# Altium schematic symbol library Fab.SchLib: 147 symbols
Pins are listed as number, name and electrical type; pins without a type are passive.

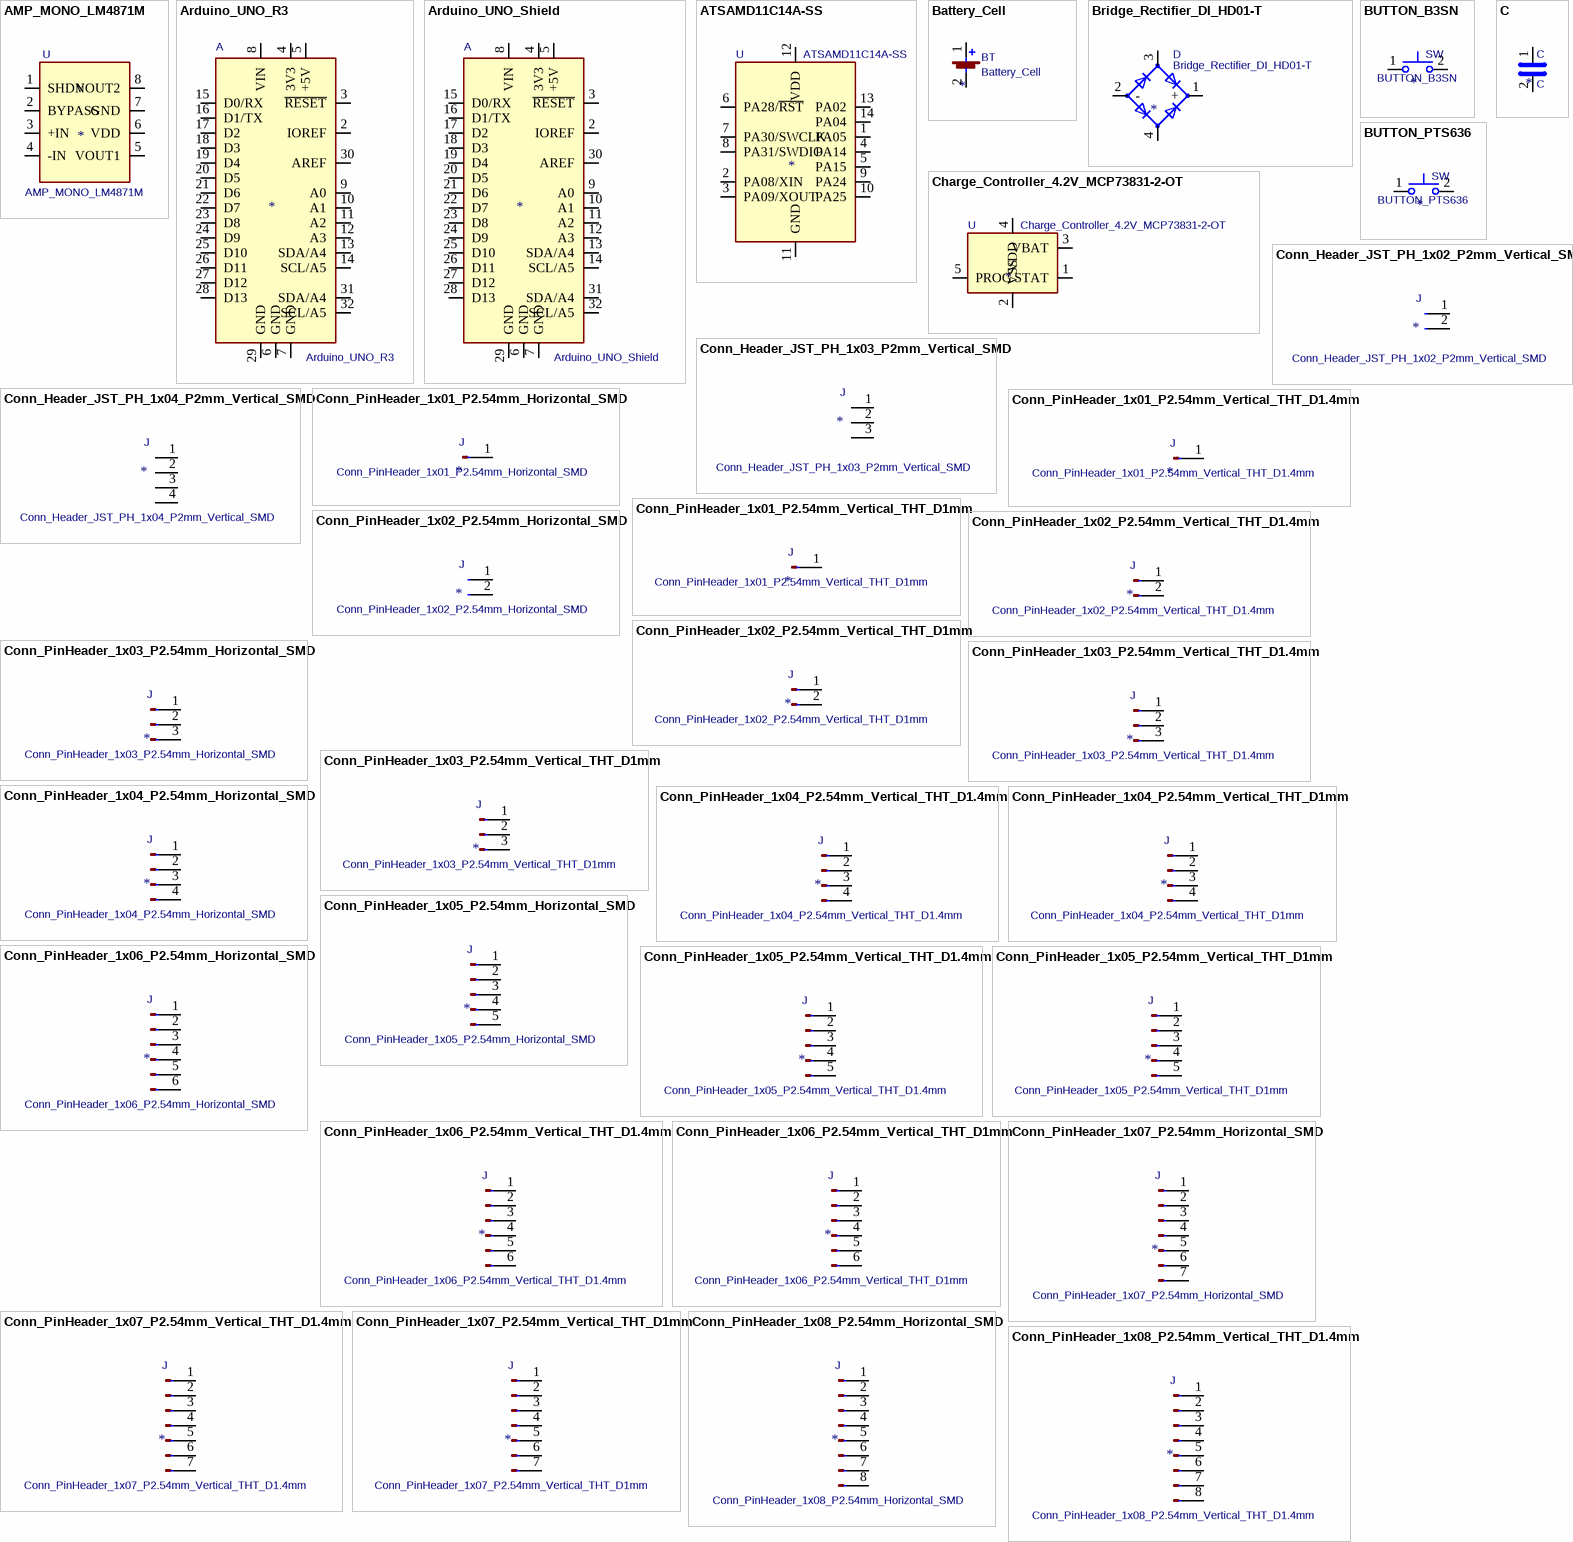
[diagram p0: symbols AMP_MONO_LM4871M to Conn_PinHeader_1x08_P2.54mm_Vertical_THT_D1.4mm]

## AMP_MONO_LM4871M
designator U  value AMP_MONO_LM4871M
footprint SOIC-8_3.9x4.9mm_P1.27mm
pins: 1 SHDN, 2 BYPASS, 3 +IN, 4 -IN, 5 VOUT1, 6 VDD, 7 GND, 8 VOUT2

## Arduino_UNO_R3
designator A  value Arduino_UNO_R3
footprint Arduino_UNO_R3_WithMountingHoles
pins: 1 NC hidden, 2 IOREF, 3 ~{RESET}, 4 3V3, 5 +5V, 6 GND, 7 GND, 8 VIN, 9 A0, 10 A1, 11 A2, 12 A3, 13 SDA/A4, 14 SCL/A5, 15 D0/RX, 16 D1/TX, 17 D2, 18 D3, 19 D4, 20 D5, 21 D6, 22 D7, 23 D8, 24 D9, 25 D10, 26 D11, 27 D12, 28 D13, 29 GND, 30 AREF, 31 SDA/A4, 32 SCL/A5

## Arduino_UNO_Shield
designator A  value Arduino_UNO_Shield
footprint Arduino_UNO_Shield
pins: 1 NC hidden, 2 IOREF, 3 ~{RESET}, 4 3V3, 5 +5V, 6 GND, 7 GND, 8 VIN, 9 A0, 10 A1, 11 A2, 12 A3, 13 SDA/A4, 14 SCL/A5, 15 D0/RX, 16 D1/TX, 17 D2, 18 D3, 19 D4, 20 D5, 21 D6, 22 D7, 23 D8, 24 D9, 25 D10, 26 D11, 27 D12, 28 D13, 29 GND, 30 AREF, 31 SDA/A4, 32 SCL/A5

## ATSAMD11C14A-SS
designator U  value ATSAMD11C14A-SS
footprint SOIC-14_3.9x8.7mm_P1.27mm
pins: 1 PA05, 2 PA08/XIN, 3 PA09/XOUT, 4 PA14, 5 PA15, 6 PA28/~{RST}, 7 PA30/SWCLK, 8 PA31/SWDIO, 9 PA24, 10 PA25, 11 GND, 12 VDD, 13 PA02, 14 PA04

## Battery_Cell
designator BT  value Battery_Cell
footprint Coin-Battery-Holder_Linx_BAT-HLD-001_D20mm
pins: 1 +, 2 -

## Bridge_Rectifier_DI_HD01-T
designator D  value Bridge_Rectifier_DI_HD01-T
footprint Bridge_Rectifier_DI_HD01-T
pins: 1 +, 2 -, 3, 4

## BUTTON_B3SN
designator SW  value BUTTON_B3SN
footprint Button_Omron_B3SN_6x6mm
pins: 1, 2

## BUTTON_PTS636
designator SW  value BUTTON_PTS636
footprint Button_C&K_PTS636_6x3.5mm
pins: 1, 2

## C
designator C  value C
footprint C_1206
pins: 1, 2

## Charge_Controller_4.2V_MCP73831-2-OT
designator U  value Charge_Controller_4.2V_MCP73831-2-OT
footprint SOT-23-5
pins: 1 STAT, 2 VSS, 3 VBAT, 4 VDD, 5 PROG

## Conn_Header_JST_PH_1x02_P2mm_Vertical_SMD
designator J  value Conn_Header_JST_PH_1x02_P2mm_Vertical_SMD
footprint Header_JST_PH_1x02_P2mm_Vertical_SMD
pins: 1, 2

## Conn_Header_JST_PH_1x03_P2mm_Vertical_SMD
designator J  value Conn_Header_JST_PH_1x03_P2mm_Vertical_SMD
footprint Header_JST_PH_1x03_P2mm_Vertical_SMD
pins: 1, 2, 3

## Conn_Header_JST_PH_1x04_P2mm_Vertical_SMD
designator J  value Conn_Header_JST_PH_1x04_P2mm_Vertical_SMD
footprint Header_JST_PH_1x04_P2mm_Vertical_SMD
pins: 1, 2, 3, 4

## Conn_PinHeader_1x01_P2.54mm_Horizontal_SMD
designator J  value Conn_PinHeader_1x01_P2.54mm_Horizontal_SMD
footprint PinHeader_1x01_P2.54mm_Horizontal_SMD
pins: 1 Pin_1

## Conn_PinHeader_1x01_P2.54mm_Vertical_THT_D1.4mm
designator J  value Conn_PinHeader_1x01_P2.54mm_Vertical_THT_D1.4mm
footprint PinHeader_1x01_P2.54mm_Vertical_THT_D1.4mm
pins: 1 Pin_1

## Conn_PinHeader_1x01_P2.54mm_Vertical_THT_D1mm
designator J  value Conn_PinHeader_1x01_P2.54mm_Vertical_THT_D1mm
footprint PinHeader_1x01_P2.54mm_Vertical_THT_D1mm
pins: 1 Pin_1

## Conn_PinHeader_1x02_P2.54mm_Horizontal_SMD
designator J  value Conn_PinHeader_1x02_P2.54mm_Horizontal_SMD
footprint PinHeader_UPDI_01x02_P2.54mm_Horizontal_SMD
pins: 1, 2

## Conn_PinHeader_1x02_P2.54mm_Vertical_THT_D1.4mm
designator J  value Conn_PinHeader_1x02_P2.54mm_Vertical_THT_D1.4mm
footprint PinHeader_1x02_P2.54mm_Vertical_THT_D1.4mm
pins: 1 Pin_1, 2 Pin_2

## Conn_PinHeader_1x02_P2.54mm_Vertical_THT_D1mm
designator J  value Conn_PinHeader_1x02_P2.54mm_Vertical_THT_D1mm
footprint PinHeader_1x02_P2.54mm_Vertical_THT_D1mm
pins: 1 Pin_1, 2 Pin_2

## Conn_PinHeader_1x03_P2.54mm_Horizontal_SMD
designator J  value Conn_PinHeader_1x03_P2.54mm_Horizontal_SMD
footprint PinHeader_1x03_P2.54mm_Horizontal_SMD
pins: 1 Pin_1, 2 Pin_2, 3 Pin_3

## Conn_PinHeader_1x03_P2.54mm_Vertical_THT_D1.4mm
designator J  value Conn_PinHeader_1x03_P2.54mm_Vertical_THT_D1.4mm
footprint PinHeader_1x03_P2.54mm_Vertical_THT_D1.4mm
pins: 1 Pin_1, 2 Pin_2, 3 Pin_3

## Conn_PinHeader_1x03_P2.54mm_Vertical_THT_D1mm
designator J  value Conn_PinHeader_1x03_P2.54mm_Vertical_THT_D1mm
footprint PinHeader_1x03_P2.54mm_Vertical_THT_D1mm
pins: 1 Pin_1, 2 Pin_2, 3 Pin_3

## Conn_PinHeader_1x04_P2.54mm_Horizontal_SMD
designator J  value Conn_PinHeader_1x04_P2.54mm_Horizontal_SMD
footprint PinHeader_1x04_P2.54mm_Horizontal_SMD
pins: 1 Pin_1, 2 Pin_2, 3 Pin_3, 4 Pin_4

## Conn_PinHeader_1x04_P2.54mm_Vertical_THT_D1.4mm
designator J  value Conn_PinHeader_1x04_P2.54mm_Vertical_THT_D1.4mm
footprint PinHeader_1x04_P2.54mm_Vertical_THT_D1.4mm
pins: 1 Pin_1, 2 Pin_2, 3 Pin_3, 4 Pin_4

## Conn_PinHeader_1x04_P2.54mm_Vertical_THT_D1mm
designator J  value Conn_PinHeader_1x04_P2.54mm_Vertical_THT_D1mm
footprint PinHeader_1x04_P2.54mm_Vertical_THT_D1mm
pins: 1 Pin_1, 2 Pin_2, 3 Pin_3, 4 Pin_4

## Conn_PinHeader_1x05_P2.54mm_Horizontal_SMD
designator J  value Conn_PinHeader_1x05_P2.54mm_Horizontal_SMD
footprint PinHeader_1x05_P2.54mm_Horizontal_SMD
pins: 1 Pin_1, 2 Pin_2, 3 Pin_3, 4 Pin_4, 5 Pin_5

## Conn_PinHeader_1x05_P2.54mm_Vertical_THT_D1.4mm
designator J  value Conn_PinHeader_1x05_P2.54mm_Vertical_THT_D1.4mm
footprint PinHeader_1x04_P2.54mm_Vertical_THT_D1.4mm
pins: 1 Pin_1, 2 Pin_2, 3 Pin_3, 4 Pin_4, 5 Pin_5

## Conn_PinHeader_1x05_P2.54mm_Vertical_THT_D1mm
designator J  value Conn_PinHeader_1x05_P2.54mm_Vertical_THT_D1mm
footprint PinHeader_1x05_P2.54mm_Vertical_THT_D1mm
pins: 1 Pin_1, 2 Pin_2, 3 Pin_3, 4 Pin_4, 5 Pin_5

## Conn_PinHeader_1x06_P2.54mm_Horizontal_SMD
designator J  value Conn_PinHeader_1x06_P2.54mm_Horizontal_SMD
footprint PinHeader_1x06_P2.54mm_Horizontal_SMD
pins: 1 Pin_1, 2 Pin_2, 3 Pin_3, 4 Pin_4, 5 Pin_5, 6 Pin_6

## Conn_PinHeader_1x06_P2.54mm_Vertical_THT_D1.4mm
designator J  value Conn_PinHeader_1x06_P2.54mm_Vertical_THT_D1.4mm
footprint PinHeader_1x06_P2.54mm_Vertical_THT_D1.4mm
pins: 1 Pin_1, 2 Pin_2, 3 Pin_3, 4 Pin_4, 5 Pin_5, 6 Pin_6

## Conn_PinHeader_1x06_P2.54mm_Vertical_THT_D1mm
designator J  value Conn_PinHeader_1x06_P2.54mm_Vertical_THT_D1mm
footprint PinHeader_1x06_P2.54mm_Vertical_THT_D1mm
pins: 1 Pin_1, 2 Pin_2, 3 Pin_3, 4 Pin_4, 5 Pin_5, 6 Pin_6

## Conn_PinHeader_1x07_P2.54mm_Horizontal_SMD
designator J  value Conn_PinHeader_1x07_P2.54mm_Horizontal_SMD
footprint PinHeader_1x07_P2.54mm_Horizontal_SMD
pins: 1 Pin_1, 2 Pin_2, 3 Pin_3, 4 Pin_4, 5 Pin_5, 6 Pin_6, 7 Pin_7

## Conn_PinHeader_1x07_P2.54mm_Vertical_THT_D1.4mm
designator J  value Conn_PinHeader_1x07_P2.54mm_Vertical_THT_D1.4mm
footprint PinHeader_1x07_P2.54mm_Vertical_THT_D1.4mm
pins: 1 Pin_1, 2 Pin_2, 3 Pin_3, 4 Pin_4, 5 Pin_5, 6 Pin_6, 7 Pin_7

## Conn_PinHeader_1x07_P2.54mm_Vertical_THT_D1mm
designator J  value Conn_PinHeader_1x07_P2.54mm_Vertical_THT_D1mm
footprint PinHeader_1x07_P2.54mm_Vertical_THT_D1mm
pins: 1 Pin_1, 2 Pin_2, 3 Pin_3, 4 Pin_4, 5 Pin_5, 6 Pin_6, 7 Pin_7

## Conn_PinHeader_1x08_P2.54mm_Horizontal_SMD
designator J  value Conn_PinHeader_1x08_P2.54mm_Horizontal_SMD
footprint PinHeader_1x08_P2.54mm_Horizontal_SMD
pins: 1 Pin_1, 2 Pin_2, 3 Pin_3, 4 Pin_4, 5 Pin_5, 6 Pin_6, 7 Pin_7, 8 Pin_8

## Conn_PinHeader_1x08_P2.54mm_Vertical_THT_D1.4mm
designator J  value Conn_PinHeader_1x08_P2.54mm_Vertical_THT_D1.4mm
footprint PinHeader_1x08_P2.54mm_Vertical_THT_D1.4mm
pins: 1 Pin_1, 2 Pin_2, 3 Pin_3, 4 Pin_4, 5 Pin_5, 6 Pin_6, 7 Pin_7, 8 Pin_8

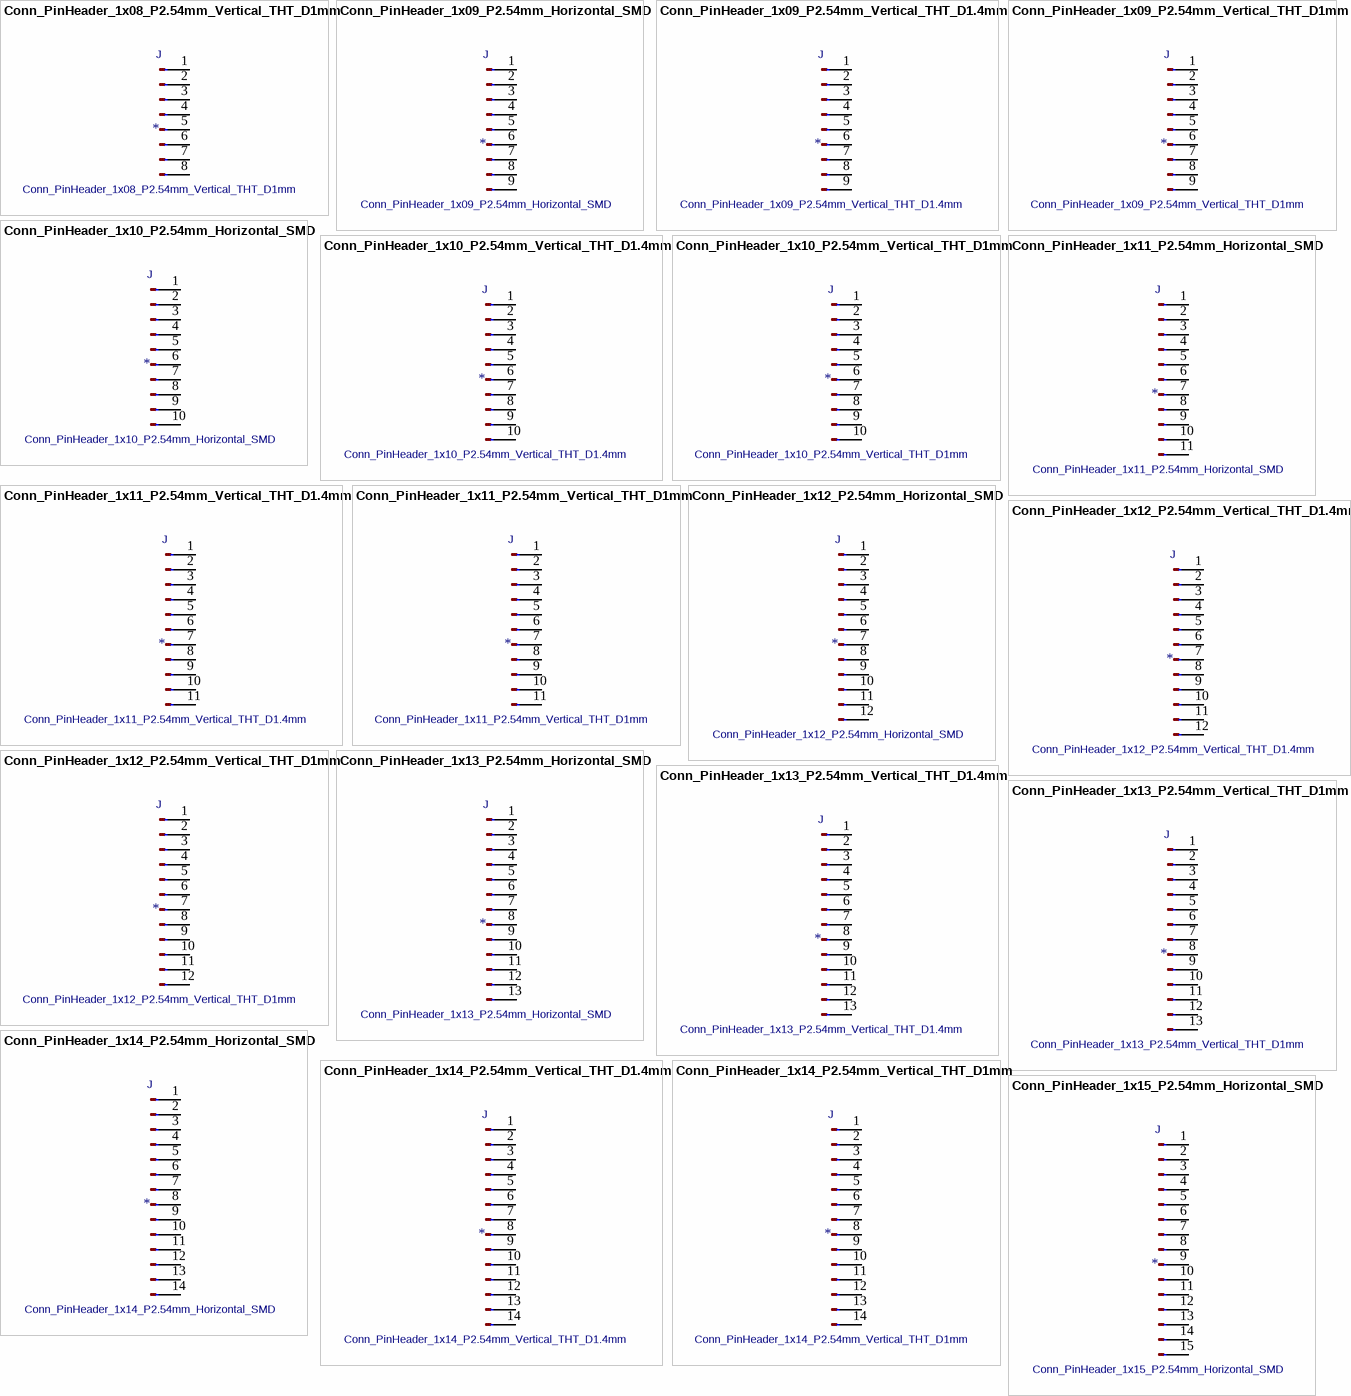
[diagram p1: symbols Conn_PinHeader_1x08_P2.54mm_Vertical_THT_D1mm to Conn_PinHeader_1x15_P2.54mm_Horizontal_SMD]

## Conn_PinHeader_1x08_P2.54mm_Vertical_THT_D1mm
designator J  value Conn_PinHeader_1x08_P2.54mm_Vertical_THT_D1mm
footprint PinHeader_1x08_P2.54mm_Vertical_THT_D1mm
pins: 1 Pin_1, 2 Pin_2, 3 Pin_3, 4 Pin_4, 5 Pin_5, 6 Pin_6, 7 Pin_7, 8 Pin_8

## Conn_PinHeader_1x09_P2.54mm_Horizontal_SMD
designator J  value Conn_PinHeader_1x09_P2.54mm_Horizontal_SMD
footprint PinHeader_1x09_P2.54mm_Horizontal_SMD
pins: 1 Pin_1, 2 Pin_2, 3 Pin_3, 4 Pin_4, 5 Pin_5, 6 Pin_6, 7 Pin_7, 8 Pin_8, 9 Pin_9

## Conn_PinHeader_1x09_P2.54mm_Vertical_THT_D1.4mm
designator J  value Conn_PinHeader_1x09_P2.54mm_Vertical_THT_D1.4mm
footprint PinHeader_1x09_P2.54mm_Vertical_THT_D1.4mm
pins: 1 Pin_1, 2 Pin_2, 3 Pin_3, 4 Pin_4, 5 Pin_5, 6 Pin_6, 7 Pin_7, 8 Pin_8, 9 Pin_9

## Conn_PinHeader_1x09_P2.54mm_Vertical_THT_D1mm
designator J  value Conn_PinHeader_1x09_P2.54mm_Vertical_THT_D1mm
footprint PinHeader_1x09_P2.54mm_Vertical_THT_D1mm
pins: 1 Pin_1, 2 Pin_2, 3 Pin_3, 4 Pin_4, 5 Pin_5, 6 Pin_6, 7 Pin_7, 8 Pin_8, 9 Pin_9

## Conn_PinHeader_1x10_P2.54mm_Horizontal_SMD
designator J  value Conn_PinHeader_1x10_P2.54mm_Horizontal_SMD
footprint PinHeader_1x10_P2.54mm_Horizontal_SMD
pins: 1 Pin_1, 2 Pin_2, 3 Pin_3, 4 Pin_4, 5 Pin_5, 6 Pin_6, 7 Pin_7, 8 Pin_8, 9 Pin_9, 10 Pin_10

## Conn_PinHeader_1x10_P2.54mm_Vertical_THT_D1.4mm
designator J  value Conn_PinHeader_1x10_P2.54mm_Vertical_THT_D1.4mm
footprint PinHeader_1x10_P2.54mm_Vertical_THT_D1.4mm
pins: 1 Pin_1, 2 Pin_2, 3 Pin_3, 4 Pin_4, 5 Pin_5, 6 Pin_6, 7 Pin_7, 8 Pin_8, 9 Pin_9, 10 Pin_10

## Conn_PinHeader_1x10_P2.54mm_Vertical_THT_D1mm
designator J  value Conn_PinHeader_1x10_P2.54mm_Vertical_THT_D1mm
footprint PinHeader_1x10_P2.54mm_Vertical_THT_D1mm
pins: 1 Pin_1, 2 Pin_2, 3 Pin_3, 4 Pin_4, 5 Pin_5, 6 Pin_6, 7 Pin_7, 8 Pin_8, 9 Pin_9, 10 Pin_10

## Conn_PinHeader_1x11_P2.54mm_Horizontal_SMD
designator J  value Conn_PinHeader_1x11_P2.54mm_Horizontal_SMD
footprint PinHeader_1x11_P2.54mm_Horizontal_SMD
pins: 1 Pin_1, 2 Pin_2, 3 Pin_3, 4 Pin_4, 5 Pin_5, 6 Pin_6, 7 Pin_7, 8 Pin_8, 9 Pin_9, 10 Pin_10, 11 Pin_11

## Conn_PinHeader_1x11_P2.54mm_Vertical_THT_D1.4mm
designator J  value Conn_PinHeader_1x11_P2.54mm_Vertical_THT_D1.4mm
footprint PinHeader_1x11_P2.54mm_Vertical_THT_D1.4mm
pins: 1 Pin_1, 2 Pin_2, 3 Pin_3, 4 Pin_4, 5 Pin_5, 6 Pin_6, 7 Pin_7, 8 Pin_8, 9 Pin_9, 10 Pin_10, 11 Pin_11

## Conn_PinHeader_1x11_P2.54mm_Vertical_THT_D1mm
designator J  value Conn_PinHeader_1x11_P2.54mm_Vertical_THT_D1mm
footprint PinHeader_1x11_P2.54mm_Vertical_THT_D1mm
pins: 1 Pin_1, 2 Pin_2, 3 Pin_3, 4 Pin_4, 5 Pin_5, 6 Pin_6, 7 Pin_7, 8 Pin_8, 9 Pin_9, 10 Pin_10, 11 Pin_11

## Conn_PinHeader_1x12_P2.54mm_Horizontal_SMD
designator J  value Conn_PinHeader_1x12_P2.54mm_Horizontal_SMD
footprint PinHeader_1x12_P2.54mm_Horizontal_SMD
pins: 1 Pin_1, 2 Pin_2, 3 Pin_3, 4 Pin_4, 5 Pin_5, 6 Pin_6, 7 Pin_7, 8 Pin_8, 9 Pin_9, 10 Pin_10, 11 Pin_11, 12 Pin_12

## Conn_PinHeader_1x12_P2.54mm_Vertical_THT_D1.4mm
designator J  value Conn_PinHeader_1x12_P2.54mm_Vertical_THT_D1.4mm
footprint PinHeader_1x12_P2.54mm_Vertical_THT_D1.4mm
pins: 1 Pin_1, 2 Pin_2, 3 Pin_3, 4 Pin_4, 5 Pin_5, 6 Pin_6, 7 Pin_7, 8 Pin_8, 9 Pin_9, 10 Pin_10, 11 Pin_11, 12 Pin_12

## Conn_PinHeader_1x12_P2.54mm_Vertical_THT_D1mm
designator J  value Conn_PinHeader_1x12_P2.54mm_Vertical_THT_D1mm
footprint PinHeader_1x12_P2.54mm_Vertical_THT_D1mm
pins: 1 Pin_1, 2 Pin_2, 3 Pin_3, 4 Pin_4, 5 Pin_5, 6 Pin_6, 7 Pin_7, 8 Pin_8, 9 Pin_9, 10 Pin_10, 11 Pin_11, 12 Pin_12

## Conn_PinHeader_1x13_P2.54mm_Horizontal_SMD
designator J  value Conn_PinHeader_1x13_P2.54mm_Horizontal_SMD
footprint PinHeader_1x13_P2.54mm_Horizontal_SMD
pins: 1 Pin_1, 2 Pin_2, 3 Pin_3, 4 Pin_4, 5 Pin_5, 6 Pin_6, 7 Pin_7, 8 Pin_8, 9 Pin_9, 10 Pin_10, 11 Pin_11, 12 Pin_12, 13 Pin_13

## Conn_PinHeader_1x13_P2.54mm_Vertical_THT_D1.4mm
designator J  value Conn_PinHeader_1x13_P2.54mm_Vertical_THT_D1.4mm
footprint PinHeader_1x13_P2.54mm_Vertical_THT_D1.4mm
pins: 1 Pin_1, 2 Pin_2, 3 Pin_3, 4 Pin_4, 5 Pin_5, 6 Pin_6, 7 Pin_7, 8 Pin_8, 9 Pin_9, 10 Pin_10, 11 Pin_11, 12 Pin_12, 13 Pin_13

## Conn_PinHeader_1x13_P2.54mm_Vertical_THT_D1mm
designator J  value Conn_PinHeader_1x13_P2.54mm_Vertical_THT_D1mm
footprint PinHeader_1x13_P2.54mm_Vertical_THT_D1mm
pins: 1 Pin_1, 2 Pin_2, 3 Pin_3, 4 Pin_4, 5 Pin_5, 6 Pin_6, 7 Pin_7, 8 Pin_8, 9 Pin_9, 10 Pin_10, 11 Pin_11, 12 Pin_12, 13 Pin_13

## Conn_PinHeader_1x14_P2.54mm_Horizontal_SMD
designator J  value Conn_PinHeader_1x14_P2.54mm_Horizontal_SMD
footprint PinHeader_1x14_P2.54mm_Horizontal_SMD
pins: 1 Pin_1, 2 Pin_2, 3 Pin_3, 4 Pin_4, 5 Pin_5, 6 Pin_6, 7 Pin_7, 8 Pin_8, 9 Pin_9, 10 Pin_10, 11 Pin_11, 12 Pin_12, 13 Pin_13, 14 Pin_14

## Conn_PinHeader_1x14_P2.54mm_Vertical_THT_D1.4mm
designator J  value Conn_PinHeader_1x14_P2.54mm_Vertical_THT_D1.4mm
footprint PinHeader_1x14_P2.54mm_Vertical_THT_D1.4mm
pins: 1 Pin_1, 2 Pin_2, 3 Pin_3, 4 Pin_4, 5 Pin_5, 6 Pin_6, 7 Pin_7, 8 Pin_8, 9 Pin_9, 10 Pin_10, 11 Pin_11, 12 Pin_12, 13 Pin_13, 14 Pin_14

## Conn_PinHeader_1x14_P2.54mm_Vertical_THT_D1mm
designator J  value Conn_PinHeader_1x14_P2.54mm_Vertical_THT_D1mm
footprint PinHeader_1x14_P2.54mm_Vertical_THT_D1mm
pins: 1 Pin_1, 2 Pin_2, 3 Pin_3, 4 Pin_4, 5 Pin_5, 6 Pin_6, 7 Pin_7, 8 Pin_8, 9 Pin_9, 10 Pin_10, 11 Pin_11, 12 Pin_12, 13 Pin_13, 14 Pin_14

## Conn_PinHeader_1x15_P2.54mm_Horizontal_SMD
designator J  value Conn_PinHeader_1x15_P2.54mm_Horizontal_SMD
footprint PinHeader_1x15_P2.54mm_Horizontal_SMD
pins: 1 Pin_1, 2 Pin_2, 3 Pin_3, 4 Pin_4, 5 Pin_5, 6 Pin_6, 7 Pin_7, 8 Pin_8, 9 Pin_9, 10 Pin_10, 11 Pin_11, 12 Pin_12, 13 Pin_13, 14 Pin_14, 15 Pin_15

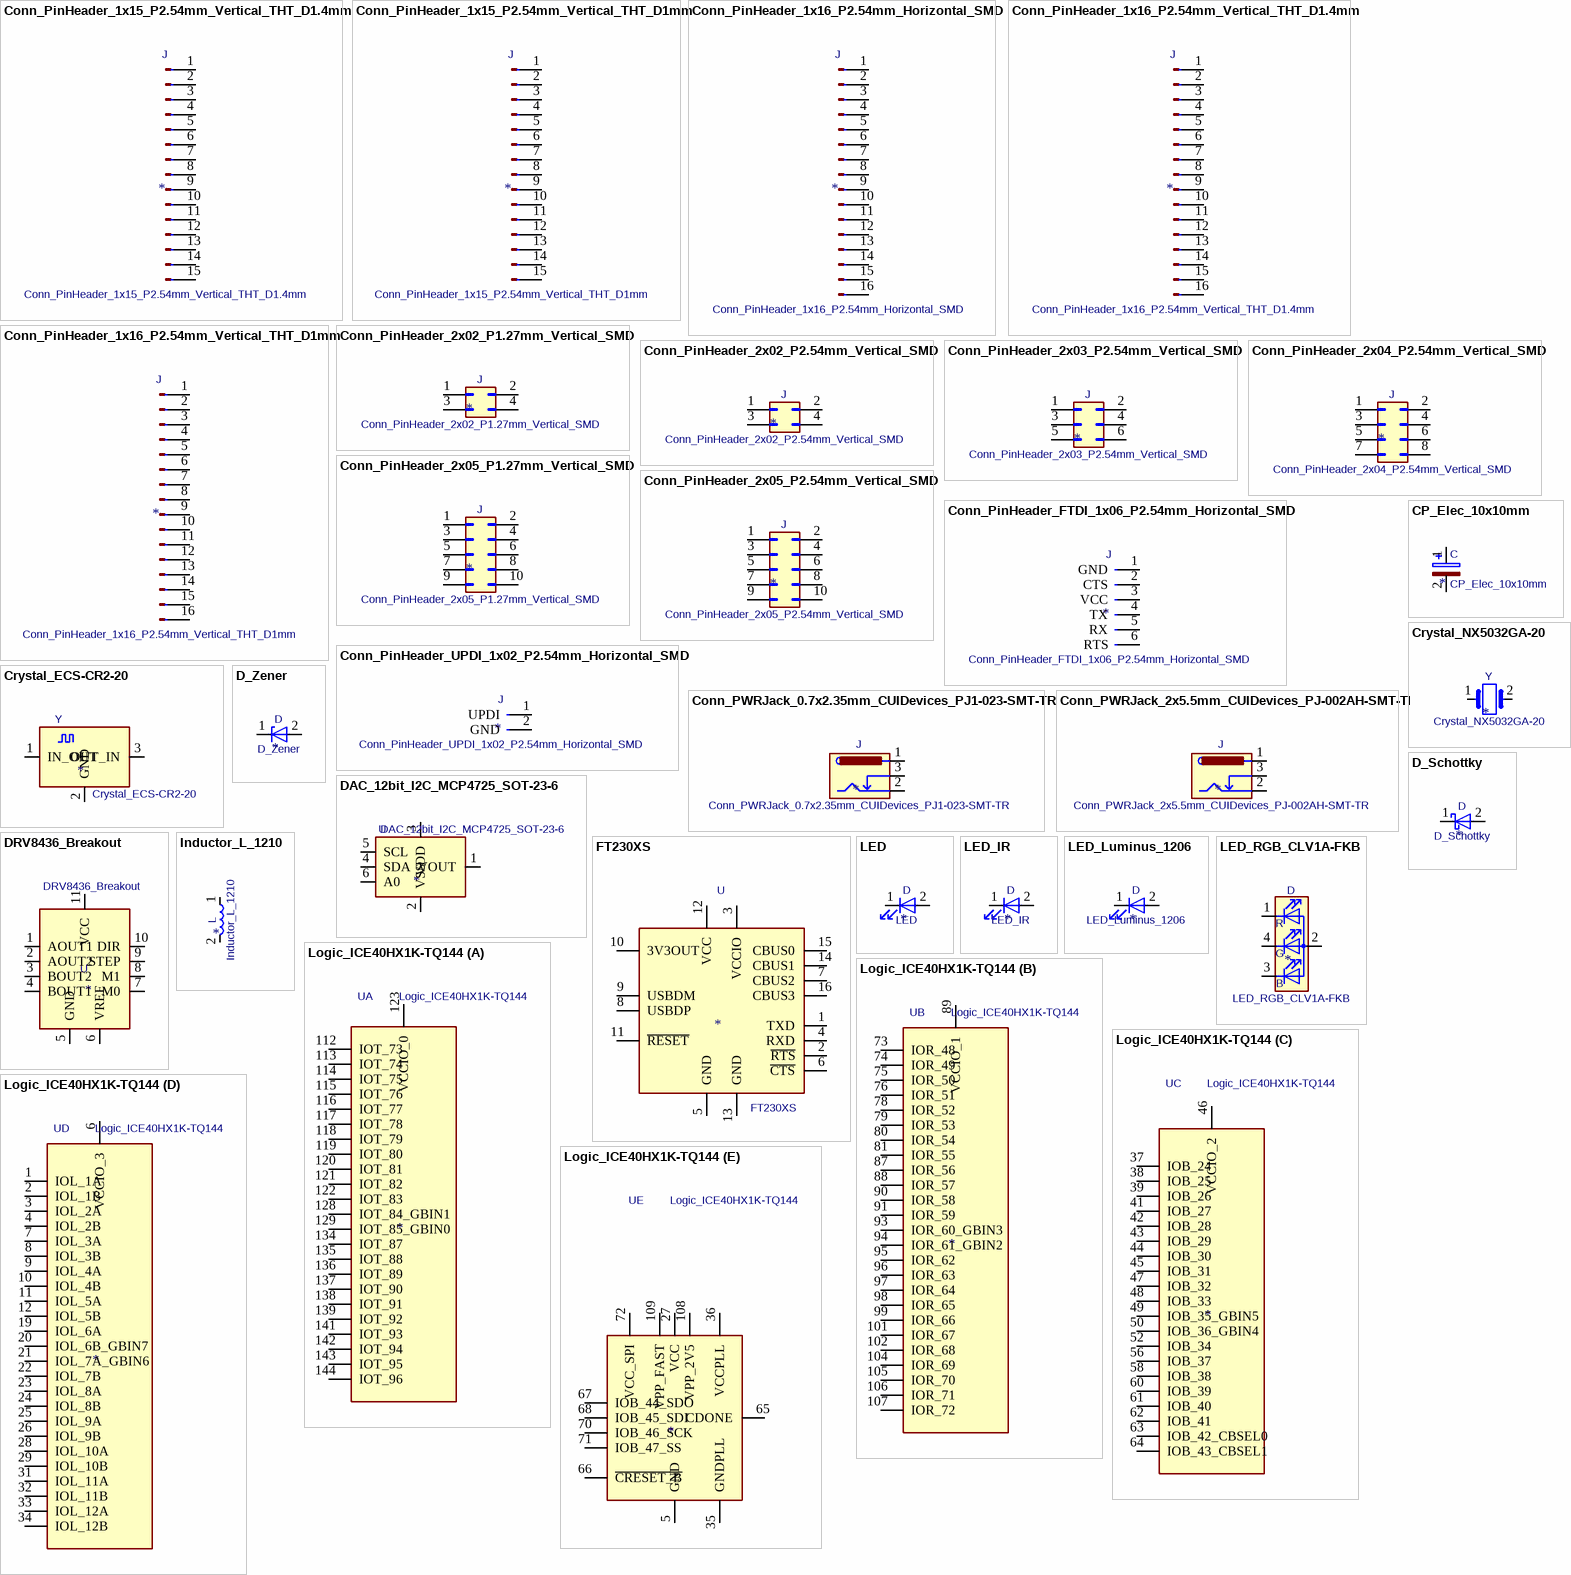
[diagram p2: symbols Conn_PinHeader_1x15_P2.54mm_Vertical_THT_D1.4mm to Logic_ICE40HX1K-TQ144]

## Conn_PinHeader_1x15_P2.54mm_Vertical_THT_D1.4mm
designator J  value Conn_PinHeader_1x15_P2.54mm_Vertical_THT_D1.4mm
footprint PinHeader_1x15_P2.54mm_Vertical_THT_D1.4mm
pins: 1 Pin_1, 2 Pin_2, 3 Pin_3, 4 Pin_4, 5 Pin_5, 6 Pin_6, 7 Pin_7, 8 Pin_8, 9 Pin_9, 10 Pin_10, 11 Pin_11, 12 Pin_12, 13 Pin_13, 14 Pin_14, 15 Pin_15

## Conn_PinHeader_1x15_P2.54mm_Vertical_THT_D1mm
designator J  value Conn_PinHeader_1x15_P2.54mm_Vertical_THT_D1mm
footprint PinHeader_1x15_P2.54mm_Vertical_THT_D1mm
pins: 1 Pin_1, 2 Pin_2, 3 Pin_3, 4 Pin_4, 5 Pin_5, 6 Pin_6, 7 Pin_7, 8 Pin_8, 9 Pin_9, 10 Pin_10, 11 Pin_11, 12 Pin_12, 13 Pin_13, 14 Pin_14, 15 Pin_15

## Conn_PinHeader_1x16_P2.54mm_Horizontal_SMD
designator J  value Conn_PinHeader_1x16_P2.54mm_Horizontal_SMD
footprint PinHeader_1x16_P2.54mm_Horizontal_SMD
pins: 1 Pin_1, 2 Pin_2, 3 Pin_3, 4 Pin_4, 5 Pin_5, 6 Pin_6, 7 Pin_7, 8 Pin_8, 9 Pin_9, 10 Pin_10, 11 Pin_11, 12 Pin_12, 13 Pin_13, 14 Pin_14, 15 Pin_15, 16 Pin_16

## Conn_PinHeader_1x16_P2.54mm_Vertical_THT_D1.4mm
designator J  value Conn_PinHeader_1x16_P2.54mm_Vertical_THT_D1.4mm
footprint PinHeader_1x16_P2.54mm_Vertical_THT_D1.4mm
pins: 1 Pin_1, 2 Pin_2, 3 Pin_3, 4 Pin_4, 5 Pin_5, 6 Pin_6, 7 Pin_7, 8 Pin_8, 9 Pin_9, 10 Pin_10, 11 Pin_11, 12 Pin_12, 13 Pin_13, 14 Pin_14, 15 Pin_15, 16 Pin_16

## Conn_PinHeader_1x16_P2.54mm_Vertical_THT_D1mm
designator J  value Conn_PinHeader_1x16_P2.54mm_Vertical_THT_D1mm
footprint PinHeader_1x16_P2.54mm_Vertical_THT_D1mm
pins: 1 Pin_1, 2 Pin_2, 3 Pin_3, 4 Pin_4, 5 Pin_5, 6 Pin_6, 7 Pin_7, 8 Pin_8, 9 Pin_9, 10 Pin_10, 11 Pin_11, 12 Pin_12, 13 Pin_13, 14 Pin_14, 15 Pin_15, 16 Pin_16

## Conn_PinHeader_2x02_P1.27mm_Vertical_SMD
designator J  value Conn_PinHeader_2x02_P1.27mm_Vertical_SMD
footprint PinHeader_2x02_P1.27mm_Vertical_SMD
pins: 1 Pin_1, 2 Pin_2, 3 Pin_3, 4 Pin_4

## Conn_PinHeader_2x02_P2.54mm_Vertical_SMD
designator J  value Conn_PinHeader_2x02_P2.54mm_Vertical_SMD
footprint PinHeader_2x02_P2.54mm_Vertical_SMD
pins: 1 Pin_1, 2 Pin_2, 3 Pin_3, 4 Pin_4

## Conn_PinHeader_2x03_P2.54mm_Vertical_SMD
designator J  value Conn_PinHeader_2x03_P2.54mm_Vertical_SMD
footprint PinHeader_2x03_P2.54mm_Vertical_SMD
pins: 1 Pin_1, 2 Pin_2, 3 Pin_3, 4 Pin_4, 5 Pin_5, 6 Pin_6

## Conn_PinHeader_2x04_P2.54mm_Vertical_SMD
designator J  value Conn_PinHeader_2x04_P2.54mm_Vertical_SMD
footprint PinHeader_2x04_P2.54mm_Vertical_SMD
pins: 1 Pin_1, 2 Pin_2, 3 Pin_3, 4 Pin_4, 5 Pin_5, 6 Pin_6, 7 Pin_7, 8 Pin_8

## Conn_PinHeader_2x05_P1.27mm_Vertical_SMD
designator J  value Conn_PinHeader_2x05_P1.27mm_Vertical_SMD
footprint PinHeader_2x05_P1.27mm_Vertical_SMD
pins: 1 Pin_1, 2 Pin_2, 3 Pin_3, 4 Pin_4, 5 Pin_5, 6 Pin_6, 7 Pin_7, 8 Pin_8, 9 Pin_9, 10 Pin_10

## Conn_PinHeader_2x05_P2.54mm_Vertical_SMD
designator J  value Conn_PinHeader_2x05_P2.54mm_Vertical_SMD
footprint PinHeader_2x05_P2.54mm_Vertical_SMD
pins: 1 Pin_1, 2 Pin_2, 3 Pin_3, 4 Pin_4, 5 Pin_5, 6 Pin_6, 7 Pin_7, 8 Pin_8, 9 Pin_9, 10 Pin_10

## Conn_PinHeader_FTDI_1x06_P2.54mm_Horizontal_SMD
designator J  value Conn_PinHeader_FTDI_1x06_P2.54mm_Horizontal_SMD
footprint PinHeader_FTDI_01x06_P2.54mm_Horizontal_SMD
pins: 1 GND, 2 CTS, 3 VCC, 4 TX, 5 RX, 6 RTS

## Conn_PinHeader_UPDI_1x02_P2.54mm_Horizontal_SMD
designator J  value Conn_PinHeader_UPDI_1x02_P2.54mm_Horizontal_SMD
footprint PinHeader_UPDI_01x02_P2.54mm_Horizontal_SMD
pins: 1 UPDI, 2 GND

## Conn_PWRJack_0.7x2.35mm_CUIDevices_PJ1-023-SMT-TR
designator J  value Conn_PWRJack_0.7x2.35mm_CUIDevices_PJ1-023-SMT-TR
footprint CUIDevices_PJ1-023-SMT-TR_PWRJack_0.7x2.35mm
pins: 1, 2, 3

## Conn_PWRJack_2x5.5mm_CUIDevices_PJ-002AH-SMT-TR
designator J  value Conn_PWRJack_2x5.5mm_CUIDevices_PJ-002AH-SMT-TR
footprint CUIDevices_PJ-002AH-SMT-TR_PWRJack_2x5.5mm
pins: 1, 2, 3

## CP_Elec_10x10mm
designator C  value CP_Elec_10x10mm
footprint CP_Elec_10x10mm
pins: 1, 2

## Crystal_ECS-CR2-20
designator Y  value Crystal_ECS-CR2-20
footprint ECS-CR2-20
pins: 1 IN_OUT, 2 GND, 3 OUT_IN

## Crystal_NX5032GA-20
designator Y  value Crystal_NX5032GA-20
footprint Crystal_NX5032GA-20
pins: 1, 2

## D_Schottky
designator D  value D_Schottky
footprint SOD-123
pins: 1 K, 2 A

## D_Zener
designator D  value D_Zener
footprint SOD-123
pins: 1 K, 2 A

## DAC_12bit_I2C_MCP4725_SOT-23-6
designator U  value DAC_12bit_I2C_MCP4725_SOT-23-6
footprint SOT-23-6
pins: 1 VOUT, 2 VSS, 3 VDD, 4 SDA, 5 SCL, 6 A0

## DRV8436_Breakout
designator U  value DRV8436_Breakout
pins: 1 AOUT1, 2 AOUT2, 3 BOUT2, 4 BOUT1, 5 GND, 6 VREF, 7 M0, 8 M1, 9 STEP, 10 DIR, 11 VCC

## FT230XS
designator U  value FT230XS
footprint SSOP-16_3.9x4.9_P0.65mm
pins: 1 TXD, 2 ~{RTS}, 3 VCCIO, 4 RXD, 5 GND, 6 ~{CTS}, 7 CBUS2, 8 USBDP, 9 USBDM, 10 3V3OUT, 11 ~{RESET}, 12 VCC, 13 GND, 14 CBUS1, 15 CBUS0, 16 CBUS3

## Inductor_L_1210
designator L  value Inductor_L_1210
footprint L_1210
pins: 1, 2

## LED
designator D  value LED
footprint LED_1206
pins: 1 K, 2 A

## LED_IR
designator D  value LED_IR
footprint LED_1206
pins: 1 K, 2 A

## LED_Luminus_1206
designator D  value LED_Luminus_1206
footprint LED_Luminus_1206
pins: 1 K, 2 A

## LED_RGB_CLV1A-FKB
designator D  value LED_RGB_CLV1A-FKB
footprint LED_RGB_Cree_CLV1A-FKB_3.2x2.8mm
pins: 1 RK, 2 A, 3 BK, 4 GK

## Logic_ICE40HX1K-TQ144
designator U  value Logic_ICE40HX1K-TQ144
footprint TQFP-144_20x20mm_P0.5mm
part A pins: 15 NC hidden, 16 NC hidden, 17 NC hidden, 18 NC hidden, 77 NC hidden, 112 IOT_73, 113 IOT_74, 114 IOT_75, 115 IOT_76, 116 IOT_77, 117 IOT_78, 118 IOT_79, 119 IOT_80, 120 IOT_81, 121 IOT_82, 122 IOT_83, 123 VCCIO_0, 128 IOT_84_GBIN1, 129 IOT_85_GBIN0, 133 VCCIO_0 hidden, 134 IOT_87, 135 IOT_88, 136 IOT_89, 137 IOT_90, 138 IOT_91, 139 IOT_92, 141 IOT_93, 142 IOT_94, 143 IOT_95, 144 IOT_96
part B pins: 40 NC hidden, 53 NC hidden, 54 NC hidden, 55 NC hidden, 73 IOR_48, 74 IOR_49, 75 IOR_50, 76 IOR_51, 78 IOR_52, 79 IOR_53, 80 IOR_54, 81 IOR_55, 82 NC hidden, 87 IOR_56, 88 IOR_57, 89 VCCIO_1, 90 IOR_58, 91 IOR_59, 93 IOR_60_GBIN3, 94 IOR_61_GBIN2, 95 IOR_62, 96 IOR_63, 97 IOR_64, 98 IOR_65, 99 IOR_66, 100 VCCIO_1 hidden, 101 IOR_67, 102 IOR_68, 104 IOR_69, 105 IOR_70, 106 IOR_71, 107 IOR_72
part C pins: 37 IOB_24, 38 IOB_25, 39 IOB_26, 41 IOB_27, 42 IOB_28, 43 IOB_29, 44 IOB_30, 45 IOB_31, 46 VCCIO_2, 47 IOB_32, 48 IOB_33, 49 IOB_35_GBIN5, 50 IOB_36_GBIN4, 52 IOB_34, 56 IOB_37, 57 VCCIO_2 hidden, 58 IOB_38, 60 IOB_39, 61 IOB_40, 62 IOB_41, 63 IOB_42_CBSEL0, 64 IOB_43_CBSEL1, 83 NC hidden, 84 NC hidden, 85 NC hidden, 110 NC hidden, 124 NC hidden
part D pins: 1 IOL_1A, 2 IOL_1B, 3 IOL_2A, 4 IOL_2B, 6 VCCIO_3, 7 IOL_3A, 8 IOL_3B, 9 IOL_4A, 10 IOL_4B, 11 IOL_5A, 12 IOL_5B, 19 IOL_6A, 20 IOL_6B_GBIN7, 21 IOL_7A_GBIN6, 22 IOL_7B, 23 IOL_8A, 24 IOL_8B, 25 IOL_9A, 26 IOL_9B, 28 IOL_10A, 29 IOL_10B, 30 VCCIO_3 hidden, 31 IOL_11A, 32 IOL_11B, 33 IOL_12A, 34 IOL_12B, 125 NC hidden, 126 NC hidden, 127 NC hidden, 130 NC hidden, 131 NC hidden
part E pins: 5 GND, 13 GND hidden, 14 GND hidden, 27 VCC, 35 GNDPLL, 36 VCCPLL, 51 VCC hidden, 59 GND hidden, 65 CDONE, 66 ~{CRESET_B}, 67 IOB_44_SDO, 68 IOB_45_SDI, 69 GND hidden, 70 IOB_46_SCK, 71 IOB_47_SS, 72 VCC_SPI, 86 GND hidden, 92 VCC hidden, 103 GND hidden, 108 VPP_2V5, 109 VPP_FAST, 111 VCC hidden, 132 GND hidden, 140 GND hidden

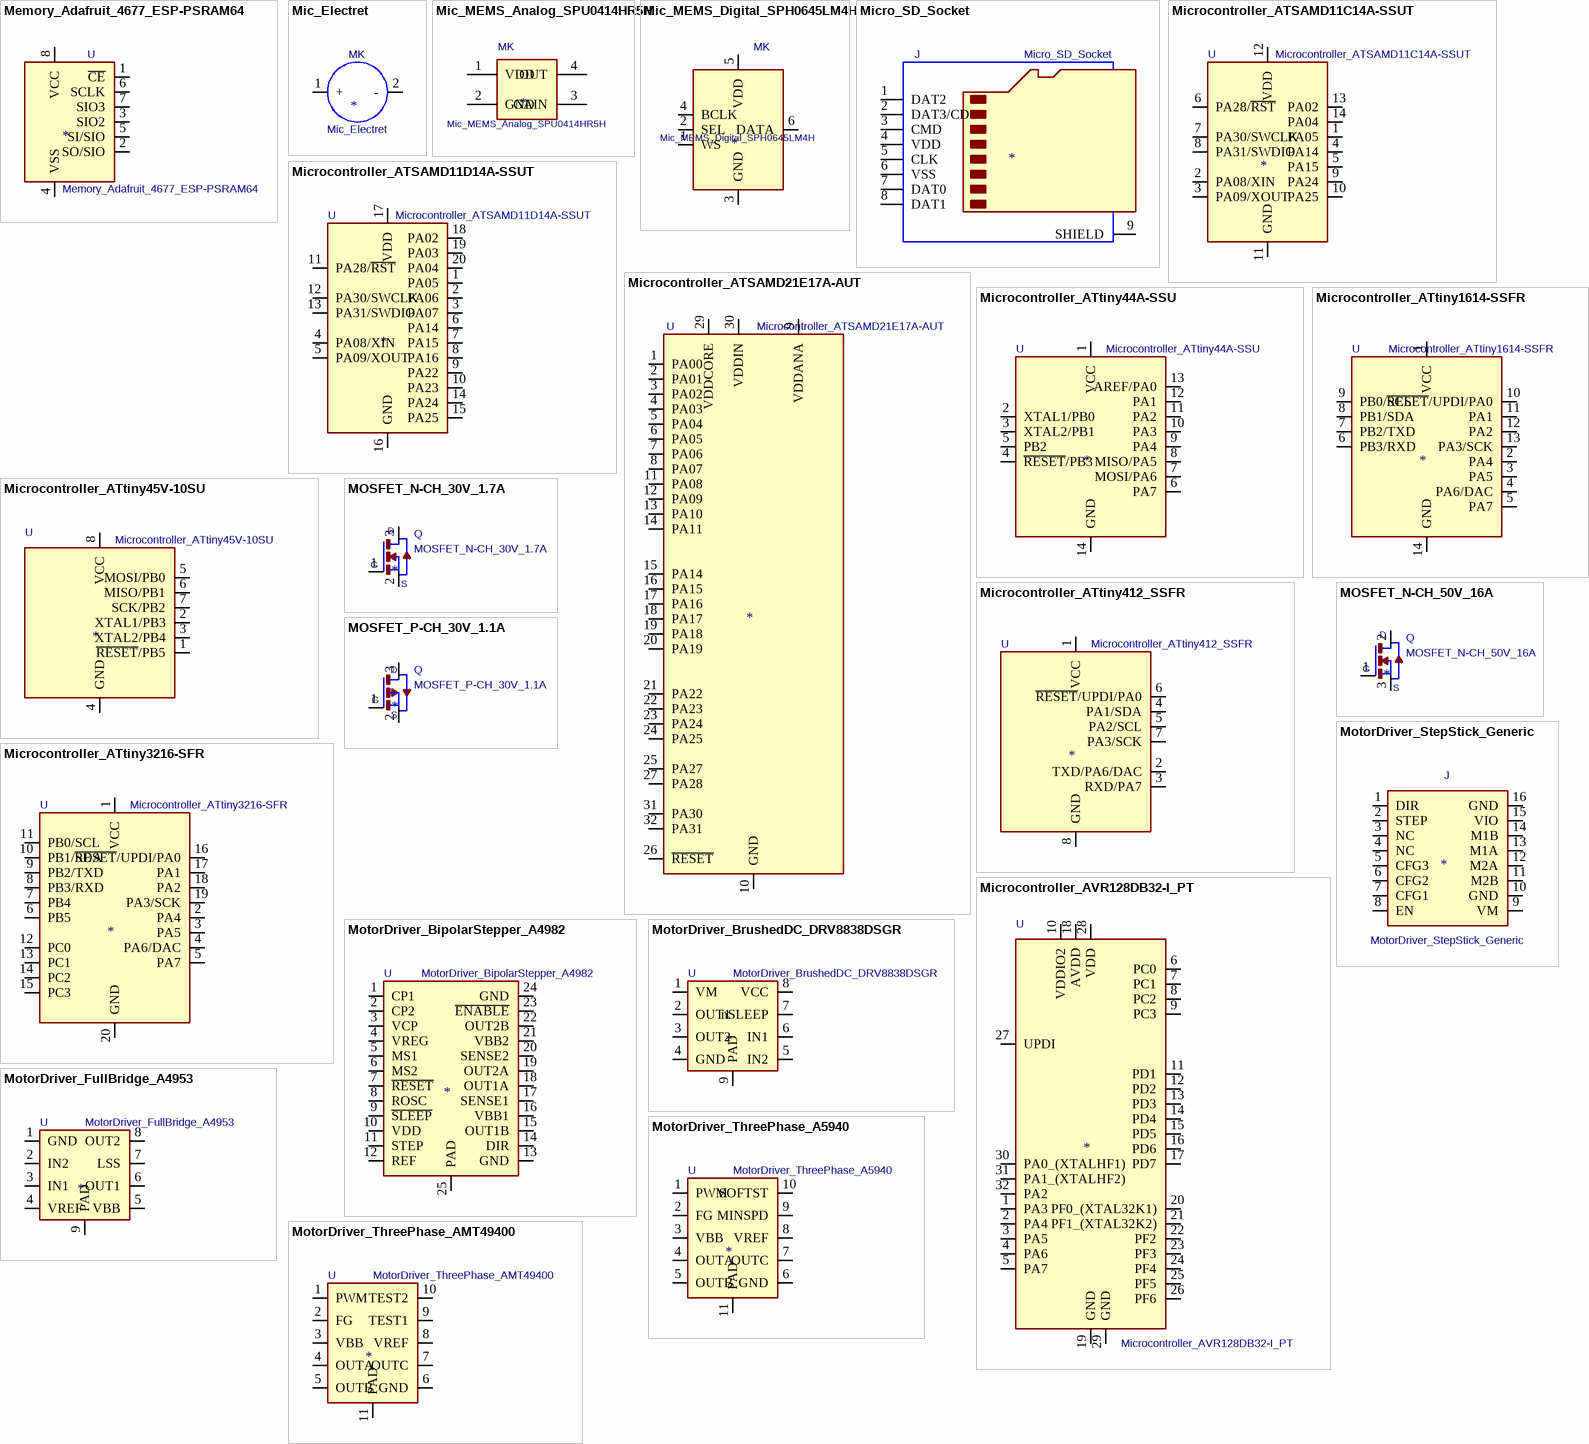
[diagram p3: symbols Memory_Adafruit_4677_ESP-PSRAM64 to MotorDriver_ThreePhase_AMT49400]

## Memory_Adafruit_4677_ESP-PSRAM64
designator U  value Memory_Adafruit_4677_ESP-PSRAM64
footprint SOIC-8_3.9x4.9mm_P1.27mm
pins: 1 ~{CE}, 2 SO/SIO, 3 SIO2, 4 VSS, 5 SI/SIO, 6 SCLK, 7 SIO3, 8 VCC

## Mic_Electret
designator MK  value Mic_Electret
footprint PinHeader_1x02_P2.54mm_Horizontal_SMD
pins: 1 +, 2 -

## Mic_MEMS_Analog_SPU0414HR5H
designator MK  value Mic_MEMS_Analog_SPU0414HR5H
footprint Mic_MEMS_Analog_Knowles_SPU0414HR5H
pins: 1 VDD, 2 GND, 3 GAIN, 4 OUT

## Mic_MEMS_Digital_SPH0645LM4H
designator MK  value Mic_MEMS_Digital_SPH0645LM4H
footprint Mic_MEMS_Digital_Knowles_SPH0645LM4H
pins: 1 WS, 2 SEL, 3 GND, 4 BCLK, 5 VDD, 6 DATA

## Micro_SD_Socket
designator J  value Micro_SD_Socket
footprint MicroSD_Amphenol_114-00841-68
pins: 1 DAT2, 2 DAT3/CD, 3 CMD, 4 VDD, 5 CLK, 6 VSS, 7 DAT0, 8 DAT1, 9 SHIELD

## Microcontroller_ATSAMD11C14A-SSUT
designator U  value Microcontroller_ATSAMD11C14A-SSUT
footprint SOIC-14_3.9x8.7mm_P1.27mm
pins: 1 PA05, 2 PA08/XIN, 3 PA09/XOUT, 4 PA14, 5 PA15, 6 PA28/~{RST}, 7 PA30/SWCLK, 8 PA31/SWDIO, 9 PA24, 10 PA25, 11 GND, 12 VDD, 13 PA02, 14 PA04

## Microcontroller_ATSAMD11D14A-SSUT
designator U  value Microcontroller_ATSAMD11D14A-SSUT
footprint SOIC-20_7.5x12.8mm_P1.27mm
pins: 1 PA05, 2 PA06, 3 PA07, 4 PA08/XIN, 5 PA09/XOUT, 6 PA14, 7 PA15, 8 PA16, 9 PA22, 10 PA23, 11 PA28/~{RST}, 12 PA30/SWCLK, 13 PA31/SWDIO, 14 PA24, 15 PA25, 16 GND, 17 VDD, 18 PA02, 19 PA03, 20 PA04

## Microcontroller_ATSAMD21E17A-AUT
designator U  value Microcontroller_ATSAMD21E17A-AUT
footprint TQFP-32_7x7mm_P0.8mm
pins: 1 PA00, 2 PA01, 3 PA02, 4 PA03, 5 PA04, 6 PA05, 7 PA06, 8 PA07, 9 VDDANA, 10 GND, 11 PA08, 12 PA09, 13 PA10, 14 PA11, 15 PA14, 16 PA15, 17 PA16, 18 PA17, 19 PA18, 20 PA19, 21 PA22, 22 PA23, 23 PA24, 24 PA25, 25 PA27, 26 ~{RESET}, 27 PA28, 28 GND hidden, 29 VDDCORE, 30 VDDIN, 31 PA30, 32 PA31

## Microcontroller_ATtiny44A-SSU
designator U  value Microcontroller_ATtiny44A-SSU
footprint SOIC-14_3.9x8.7mm_P1.27mm
pins: 1 VCC, 2 XTAL1/PB0, 3 XTAL2/PB1, 4 ~{RESET}/PB3, 5 PB2, 6 PA7, 7 MOSI/PA6, 8 MISO/PA5, 9 PA4, 10 PA3, 11 PA2, 12 PA1, 13 AREF/PA0, 14 GND

## Microcontroller_ATtiny45V-10SU
designator U  value Microcontroller_ATtiny45V-10SU
footprint SOIC-8_3.9x4.9mm_P1.27mm
pins: 1 ~{RESET}/PB5, 2 XTAL1/PB3, 3 XTAL2/PB4, 4 GND, 5 MOSI/PB0, 6 MISO/PB1, 7 SCK/PB2, 8 VCC

## Microcontroller_ATtiny412_SSFR
designator U  value Microcontroller_ATtiny412_SSFR
footprint SOIC-8_3.9x4.9mm_P1.27mm
pins: 1 VCC, 2 TXD/PA6/DAC, 3 RXD/PA7, 4 PA1/SDA, 5 PA2/SCL, 6 ~{RESET}/UPDI/PA0, 7 PA3/SCK, 8 GND

## Microcontroller_ATtiny1614-SSFR
designator U  value Microcontroller_ATtiny1614-SSFR
footprint SOIC-14_3.9x8.7mm_P1.27mm
pins: 1 VCC, 2 PA4, 3 PA5, 4 PA6/DAC, 5 PA7, 6 PB3/RXD, 7 PB2/TXD, 8 PB1/SDA, 9 PB0/SCL, 10 ~{RESET}/UPDI/PA0, 11 PA1, 12 PA2, 13 PA3/SCK, 14 GND

## Microcontroller_ATtiny3216-SFR
designator U  value Microcontroller_ATtiny3216-SFR
footprint SOIC-20_7.5x12.8mm_P1.27mm
pins: 1 VCC, 2 PA4, 3 PA5, 4 PA6/DAC, 5 PA7, 6 PB5, 7 PB4, 8 PB3/RXD, 9 PB2/TXD, 10 PB1/SDA, 11 PB0/SCL, 12 PC0, 13 PC1, 14 PC2, 15 PC3, 16 ~{RESET}/UPDI/PA0, 17 PA1, 18 PA2, 19 PA3/SCK, 20 GND

## Microcontroller_AVR128DB32-I_PT
designator U  value Microcontroller_AVR128DB32-I_PT
footprint TQFP-32_7x7mm_P0.8mm
pins: 1 PA3, 2 PA4, 3 PA5, 4 PA6, 5 PA7, 6 PC0, 7 PC1, 8 PC2, 9 PC3, 10 VDDIO2, 11 PD1, 12 PD2, 13 PD3, 14 PD4, 15 PD5, 16 PD6, 17 PD7, 18 AVDD, 19 GND, 20 PF0_(XTAL32K1), 21 PF1_(XTAL32K2), 22 PF2, 23 PF3, 24 PF4, 25 PF5, 26 PF6, 27 UPDI, 28 VDD, 29 GND, 30 PA0_(XTALHF1), 31 PA1_(XTALHF2), 32 PA2

## MOSFET_N-CH_30V_1.7A
designator Q  value MOSFET_N-CH_30V_1.7A
footprint SOT-23
pins: 1 G, 2 S, 3 D

## MOSFET_N-CH_50V_16A
designator Q  value MOSFET_N-CH_50V_16A
footprint TO-252
pins: 1 G, 2 D, 3 S

## MOSFET_P-CH_30V_1.1A
designator Q  value MOSFET_P-CH_30V_1.1A
footprint SOT-23
pins: 1 G, 2 S, 3 D

## MotorDriver_BipolarStepper_A4982
designator U  value MotorDriver_BipolarStepper_A4982
footprint 24-TSSOP-EP
pins: 1 CP1, 2 CP2, 3 VCP, 4 VREG, 5 MS1, 6 MS2, 7 ~{RESET}, 8 ROSC, 9 ~{SLEEP}, 10 VDD, 11 STEP, 12 REF, 13 GND, 14 DIR, 15 OUT1B, 16 VBB1, 17 SENSE1, 18 OUT1A, 19 OUT2A, 20 SENSE2, 21 VBB2, 22 OUT2B, 23 ~{ENABLE}, 24 GND, 25 PAD

## MotorDriver_BrushedDC_DRV8838DSGR
designator U  value MotorDriver_BrushedDC_DRV8838DSGR
footprint WSON-8_2x2mm_P0.5mm_EP0.9x1.6mm
pins: 1 VM, 2 OUT1, 3 OUT2, 4 GND, 5 IN2, 6 IN1, 7 nSLEEP, 8 VCC, 9 PAD

## MotorDriver_FullBridge_A4953
designator U  value MotorDriver_FullBridge_A4953
footprint SOIC-8_3.9x4.9mm_P1.27mm_EP2.41x3.3mm
pins: 1 GND, 2 IN2, 3 IN1, 4 VREF, 5 VBB, 6 OUT1, 7 LSS, 8 OUT2, 9 PAD

## MotorDriver_StepStick_Generic
designator J  value MotorDriver_StepStick_Generic
footprint Conn_StepStick
pins: 1 DIR, 2 STEP, 3 NC, 4 NC, 5 CFG3, 6 CFG2, 7 CFG1, 8 EN, 9 VM, 10 GND, 11 M2B, 12 M2A, 13 M1A, 14 M1B, 15 VIO, 16 GND

## MotorDriver_ThreePhase_A5940
designator U  value MotorDriver_ThreePhase_A5940
footprint 10-SOIC-EP_3.9x4.9mm_P1mm_EP2.41x3.3mm
pins: 1 PWM, 2 FG, 3 VBB, 4 OUTA, 5 OUTB, 6 GND, 7 OUTC, 8 VREF, 9 MINSPD, 10 SOFTST, 11 PAD

## MotorDriver_ThreePhase_AMT49400
designator U  value MotorDriver_ThreePhase_AMT49400
footprint 10-SOIC-EP_3.9x4.9mm_P1mm_EP2.41x3.3mm
pins: 1 PWM, 2 FG, 3 VBB, 4 OUTA, 5 OUTB, 6 GND, 7 OUTC, 8 VREF, 9 TEST1, 10 TEST2, 11 PAD

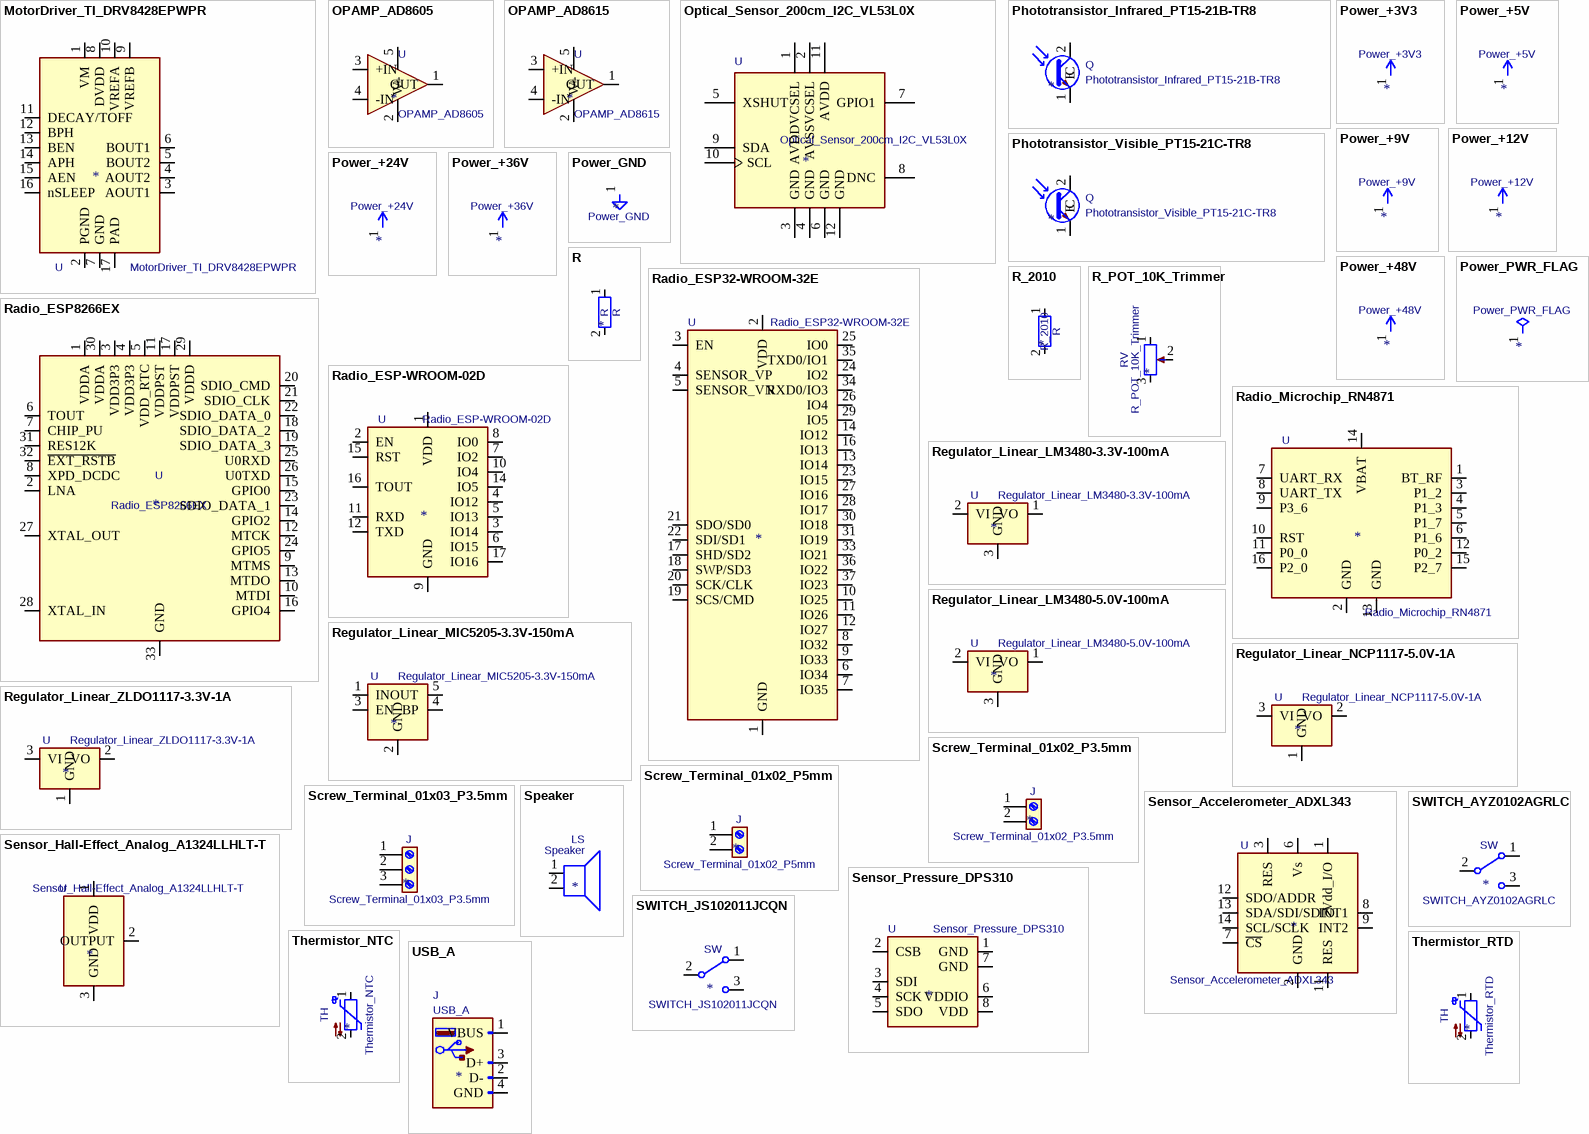
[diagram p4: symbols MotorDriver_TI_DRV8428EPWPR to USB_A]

## MotorDriver_TI_DRV8428EPWPR
designator U  value MotorDriver_TI_DRV8428EPWPR
footprint HTSSOP-16
pins: 1 VM, 2 PGND, 3 AOUT1, 4 AOUT2, 5 BOUT2, 6 BOUT1, 7 GND, 8 DVDD, 9 VREFB, 10 VREFA, 11 DECAY/TOFF, 12 BPH, 13 BEN, 14 APH, 15 AEN, 16 nSLEEP, 17 PAD

## OPAMP_AD8605
designator U  value OPAMP_AD8605
footprint SOT-23-5
pins: 1 OUT, 2 V-, 3 +IN, 4 -IN, 5 V+

## OPAMP_AD8615
designator U  value OPAMP_AD8615
footprint TSOT-23-5
pins: 1 OUT, 2 V-, 3 +IN, 4 -IN, 5 V+

## Optical_Sensor_200cm_I2C_VL53L0X
designator U  value Optical_Sensor_200cm_I2C_VL53L0X
footprint Optical_Sensor_200cm_I2C_VL53L0X
pins: 1 AVDDVCSEL, 2 AVSSVCSEL, 3 GND, 4 GND, 5 XSHUT, 6 GND, 7 GPIO1, 8 DNC, 9 SDA, 10 SCL, 11 AVDD, 12 GND

## Phototransistor_Infrared_PT15-21B-TR8
designator Q  value Phototransistor_Infrared_PT15-21B-TR8
footprint Q_1206
pins: 1 E, 2 C

## Phototransistor_Visible_PT15-21C-TR8
designator Q  value Phototransistor_Visible_PT15-21C-TR8
footprint Q_1206
pins: 1 E, 2 C

## Power_+3V3
designator #PWR  value Power_+3V3
pins: 1 +3V3

## Power_+5V
designator #PWR  value Power_+5V
pins: 1 +5V

## Power_+9V
designator #PWR  value Power_+9V
pins: 1 +9V

## Power_+12V
designator #PWR  value Power_+12V
pins: 1 +12V

## Power_+24V
designator #PWR  value Power_+24V
pins: 1 +24V

## Power_+36V
designator #PWR  value Power_+36V
pins: 1 +36V

## Power_+48V
designator #PWR  value Power_+48V
pins: 1 +48V

## Power_GND
designator #PWR  value Power_GND
pins: 1 GND

## Power_PWR_FLAG
designator #FLG  value Power_PWR_FLAG
pins: 1 pwr

## R
designator R  value R
footprint R_1206
pins: 1, 2

## R_2010
designator R  value R_2010
footprint R_2010
pins: 1, 2

## R_POT_10K_Trimmer
designator RV  value R_POT_10K_Trimmer
footprint Potentiometer_TT_Model-23_4.5x5.0x3.0mm
pins: 1, 2, 3

## Radio_ESP32-WROOM-32E
designator U  value Radio_ESP32-WROOM-32E
footprint ESP32-WROOM-32E
pins: 1 GND, 2 VDD, 3 EN, 4 SENSOR_VP, 5 SENSOR_VN, 6 IO34, 7 IO35, 8 IO32, 9 IO33, 10 IO25, 11 IO26, 12 IO27, 13 IO14, 14 IO12, 15 GND hidden, 16 IO13, 17 SHD/SD2, 18 SWP/SD3, 19 SCS/CMD, 20 SCK/CLK, 21 SDO/SD0, 22 SDI/SD1, 23 IO15, 24 IO2, 25 IO0, 26 IO4, 27 IO16, 28 IO17, 29 IO5, 30 IO18, 31 IO19, 32 NC hidden, 33 IO21, 34 RXD0/IO3, 35 TXD0/IO1, 36 IO22, 37 IO23, 38 GND hidden, 39 GND hidden

## Radio_ESP8266EX
designator U  value Radio_ESP8266EX
footprint QFN-32_EP_5x5_Pitch0.5mm
pins: 1 VDDA, 2 LNA, 3 VDD3P3, 4 VDD3P3, 5 VDD_RTC, 6 TOUT, 7 CHIP_PU, 8 XPD_DCDC, 9 MTMS, 10 MTDI, 11 VDDPST, 12 MTCK, 13 MTDO, 14 GPIO2, 15 GPIO0, 16 GPIO4, 17 VDDPST, 18 SDIO_DATA_2, 19 SDIO_DATA_3, 20 SDIO_CMD, 21 SDIO_CLK, 22 SDIO_DATA_0, 23 SDIO_DATA_1, 24 GPIO5, 25 U0RXD, 26 U0TXD, 27 XTAL_OUT, 28 XTAL_IN, 29 VDDD, 30 VDDA, 31 RES12K, 32 ~{EXT_RSTB}, 33 GND

## Radio_ESP-WROOM-02D
designator U  value Radio_ESP-WROOM-02D
footprint ESP-WROOM-02D
pins: 1 VDD, 2 EN, 3 IO14, 4 IO12, 5 IO13, 6 IO15, 7 IO2, 8 IO0, 9 GND, 10 IO4, 11 RXD, 12 TXD, 13 GND hidden, 14 IO5, 15 RST, 16 TOUT, 17 IO16, 18 GND hidden, 19 GND hidden

## Radio_Microchip_RN4871
designator U  value Radio_Microchip_RN4871
footprint Microchip_RN4871
pins: 1 BT_RF, 2 GND, 3 P1_2, 4 P1_3, 5 P1_7, 6 P1_6, 7 UART_RX, 8 UART_TX, 9 P3_6, 10 RST, 11 P0_0, 12 P0_2, 13 GND, 14 VBAT, 15 P2_7, 16 P2_0

## Regulator_Linear_LM3480-3.3V-100mA
designator U  value Regulator_Linear_LM3480-3.3V-100mA
footprint SOT-23
pins: 1 VO, 2 VI, 3 GND

## Regulator_Linear_LM3480-5.0V-100mA
designator U  value Regulator_Linear_LM3480-5.0V-100mA
footprint SOT-23
pins: 1 VO, 2 VI, 3 GND

## Regulator_Linear_MIC5205-3.3V-150mA
designator U  value Regulator_Linear_MIC5205-3.3V-150mA
footprint SOT-23-5
pins: 1 IN, 2 GND, 3 EN, 4 BP, 5 OUT

## Regulator_Linear_NCP1117-5.0V-1A
designator U  value Regulator_Linear_NCP1117-5.0V-1A
footprint SOT-223-3_TabPin2
pins: 1 GND, 2 VO, 3 VI

## Regulator_Linear_ZLDO1117-3.3V-1A
designator U  value Regulator_Linear_ZLDO1117-3.3V-1A
footprint SOT-223-3_TabPin2
pins: 1 GND, 2 VO, 3 VI

## Screw_Terminal_01x02_P3.5mm
designator J  value Screw_Terminal_01x02_P3.5mm
footprint TerminalBlock_OnShore_1x02_P3.50mm_Horizontal
pins: 1 Pin_1, 2 Pin_2

## Screw_Terminal_01x02_P5mm
designator J  value Screw_Terminal_01x02_P5mm
footprint TerminalBlock_OnShore_1x02_P5.00mm_Horizontal
pins: 1 Pin_1, 2 Pin_2

## Screw_Terminal_01x03_P3.5mm
designator J  value Screw_Terminal_01x03_P3.5mm
footprint TerminalBlock_OnShore_1x03_P3.50mm_Horizontal
pins: 1 Pin_1, 2 Pin_2, 3 Pin_3

## Sensor_Accelerometer_ADXL343
designator U  value Sensor_Accelerometer_ADXL343
footprint LGA-14_3x5mm
pins: 1 Vdd_I/O, 2 GND, 3 RES, 4 GND hidden, 5 GND hidden, 6 Vs, 7 ~{CS}, 8 INT1, 9 INT2, 10 NC hidden, 11 RES, 12 SDO/ADDR, 13 SDA/SDI/SDIO, 14 SCL/SCLK

## Sensor_Hall-Effect_Analog_A1324LLHLT-T
designator U  value Sensor_Hall-Effect_Analog_A1324LLHLT-T
footprint SOT-23W
pins: 1 VDD, 2 OUTPUT, 3 GND

## Sensor_Pressure_DPS310
designator U  value Sensor_Pressure_DPS310
footprint VFLGA-8_2x2.5mm
pins: 1 GND, 2 CSB, 3 SDI, 4 SCK, 5 SDO, 6 VDDIO, 7 GND, 8 VDD

## Speaker
designator LS  value Speaker
footprint PinHeader_1x02_P2.54mm_Horizontal_SMD
pins: 1, 2

## SWITCH_AYZ0102AGRLC
designator SW  value SWITCH_AYZ0102AGRLC
footprint Switch_SPDT_C&K_AYZ0102AGRLC_7.2x3mm_P2.5mm
pins: 1 A, 2 B, 3 C

## SWITCH_JS102011JCQN
designator SW  value SWITCH_JS102011JCQN
footprint Switch_SPDT_C&K_JS102011JCQN_9x3.6mm_P2.5mm
pins: 1 A, 2 B, 3 C

## Thermistor_NTC
designator TH  value Thermistor_NTC
footprint R_1206
pins: 1, 2

## Thermistor_RTD
designator TH  value Thermistor_RTD
footprint R_1206
pins: 1, 2

## USB_A
designator J  value USB_A
pins: 1 VBUS, 2 D-, 3 D+, 4 GND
